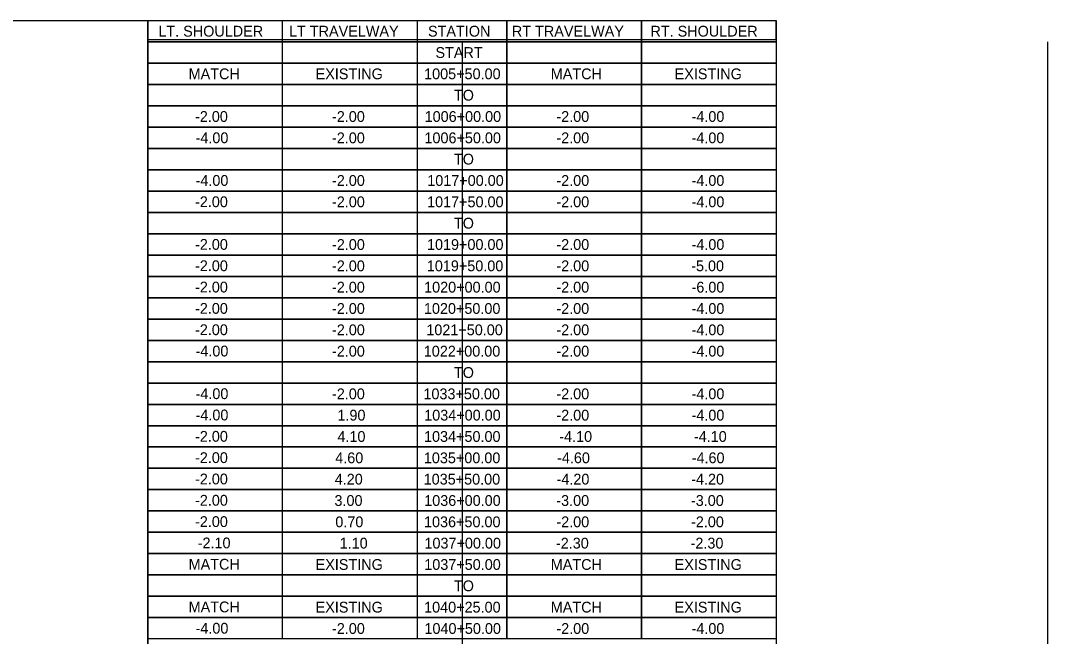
# Model space of a CAD drawing. Extents: x 1026502 to 1027102, y 781811 to 782040.
# Drawn here: x 1026944.94 to 1026990.71, y 781896.04 to 781923.49 of the extents above; entities that cross this region are included whole.
import ezdxf

# ---------------------------------------------------------------- set-up
doc = ezdxf.new("R2010")
doc.units = 0
for name, color, linetype in [('ANNOTATION', 7, 'Continuous'), ('BORDER', 7, 'Continuous'), ('DIMENSIONS', 7, 'Continuous')]:
    doc.layers.add(name, color=color, linetype=linetype)

msp = doc.modelspace()

# ---------------------------------------------------------------- linework, layer by layer
at = {"layer": 'ANNOTATION'}
for points in [[(1026917.619, 781923.493), (1026950.619, 781923.493), (1026950.619, 781846.737), (1026917.619, 781846.737)], [(1026950.619, 781923.493), (1026978.619, 781923.493), (1026978.619, 781869.32), (1026950.619, 781869.32)]]:
    msp.add_lwpolyline(points, close=True, dxfattribs=at)
at = {"layer": 'BORDER'}
for p, q in [((1026950.619, 781923.493), (1026950.619, 781922.648)), ((1026953.619, 781922.543), (1026950.619, 781922.543)), ((1026964.619, 781922.543), (1026964.619, 781816.098)), ((1026990.71, 781922.543), (1026990.71, 781816.098)), ((1026953.619, 781921.592), (1026950.619, 781921.592)), ((1026953.619, 781921.592), (1026950.619, 781921.592)), ((1026953.619, 781920.642), (1026950.619, 781920.642)), ((1026953.619, 781920.642), (1026950.619, 781920.642)), ((1026953.619, 781920.642), (1026956.619, 781920.642)), ((1026953.619, 781919.691), (1026950.619, 781919.691)), ((1026953.619, 781919.691), (1026950.619, 781919.691)), ((1026953.619, 781919.691), (1026956.619, 781919.691)), ((1026953.619, 781918.741), (1026950.619, 781918.741)), ((1026953.619, 781918.741), (1026950.619, 781918.741)), ((1026953.619, 781918.741), (1026956.619, 781918.741)), ((1026953.619, 781917.791), (1026950.619, 781917.791)), ((1026953.619, 781917.791), (1026950.619, 781917.791)), ((1026953.619, 781917.791), (1026956.619, 781917.791)), ((1026953.619, 781916.84), (1026950.619, 781916.84)), ((1026953.619, 781916.84), (1026950.619, 781916.84)), ((1026953.619, 781916.84), (1026956.619, 781916.84)), ((1026953.619, 781915.89), (1026950.619, 781915.89)), ((1026953.619, 781915.89), (1026950.619, 781915.89)), ((1026953.619, 781915.89), (1026956.619, 781915.89)), ((1026953.619, 781914.939), (1026950.619, 781914.939)), ((1026953.619, 781914.939), (1026950.619, 781914.939)), ((1026953.619, 781914.939), (1026956.619, 781914.939)), ((1026953.619, 781913.989), (1026950.619, 781913.989)), ((1026953.619, 781913.989), (1026950.619, 781913.989)), ((1026953.619, 781913.989), (1026956.619, 781913.989)), ((1026953.619, 781913.039), (1026950.619, 781913.039)), ((1026953.619, 781913.039), (1026950.619, 781913.039)), ((1026953.619, 781913.039), (1026956.619, 781913.039)), ((1026953.619, 781912.088), (1026950.619, 781912.088)), ((1026953.619, 781912.088), (1026950.619, 781912.088)), ((1026953.619, 781912.088), (1026956.619, 781912.088)), ((1026953.619, 781911.138), (1026950.619, 781911.138)), ((1026953.619, 781911.138), (1026950.619, 781911.138)), ((1026953.619, 781911.138), (1026956.619, 781911.138)), ((1026953.619, 781910.187), (1026950.619, 781910.187)), ((1026953.619, 781910.187), (1026950.619, 781910.187)), ((1026953.619, 781910.187), (1026956.619, 781910.187)), ((1026953.619, 781909.237), (1026950.619, 781909.237)), ((1026953.619, 781909.237), (1026950.619, 781909.237)), ((1026953.619, 781909.237), (1026956.619, 781909.237)), ((1026953.619, 781908.287), (1026950.619, 781908.287)), ((1026953.619, 781908.287), (1026950.619, 781908.287)), ((1026953.619, 781908.287), (1026956.619, 781908.287)), ((1026953.619, 781907.336), (1026950.619, 781907.336)), ((1026953.619, 781907.336), (1026950.619, 781907.336)), ((1026953.619, 781907.336), (1026956.619, 781907.336)), ((1026953.619, 781906.386), (1026950.619, 781906.386)), ((1026953.619, 781906.386), (1026950.619, 781906.386)), ((1026953.619, 781906.386), (1026956.619, 781906.386)), ((1026953.619, 781905.435), (1026950.619, 781905.435)), ((1026953.619, 781905.435), (1026950.619, 781905.435)), ((1026953.619, 781905.435), (1026956.619, 781905.435)), ((1026953.619, 781904.485), (1026950.619, 781904.485)), ((1026953.619, 781904.485), (1026950.619, 781904.485)), ((1026953.619, 781904.485), (1026956.619, 781904.485)), ((1026953.619, 781903.535), (1026950.619, 781903.535)), ((1026953.619, 781903.535), (1026950.619, 781903.535)), ((1026953.619, 781903.535), (1026956.619, 781903.535)), ((1026953.619, 781902.584), (1026950.619, 781902.584)), ((1026953.619, 781902.584), (1026950.619, 781902.584)), ((1026953.619, 781902.584), (1026956.619, 781902.584)), ((1026953.619, 781901.634), (1026950.619, 781901.634)), ((1026953.619, 781901.634), (1026950.619, 781901.634)), ((1026953.619, 781901.634), (1026956.619, 781901.634)), ((1026953.619, 781900.683), (1026950.619, 781900.683)), ((1026953.619, 781900.683), (1026950.619, 781900.683)), ((1026953.619, 781900.683), (1026956.619, 781900.683)), ((1026953.619, 781899.733), (1026950.619, 781899.733)), ((1026953.619, 781899.733), (1026950.619, 781899.733)), ((1026953.619, 781899.733), (1026956.619, 781899.733)), ((1026953.619, 781898.783), (1026950.619, 781898.783)), ((1026953.619, 781898.783), (1026950.619, 781898.783)), ((1026953.619, 781898.783), (1026956.619, 781898.783)), ((1026953.619, 781897.832), (1026950.619, 781897.832)), ((1026953.619, 781897.832), (1026950.619, 781897.832)), ((1026953.619, 781897.832), (1026956.619, 781897.832)), ((1026953.619, 781896.882), (1026950.619, 781896.882)), ((1026953.619, 781896.882), (1026950.619, 781896.882)), ((1026953.619, 781896.882), (1026956.619, 781896.882))]:
    msp.add_line(p, q, dxfattribs=at)
for points in [[(1026950.619, 781923.493), (1026978.619, 781923.493), (1026978.619, 781922.543), (1026950.619, 781922.543)], [(1026950.619, 781922.543), (1026978.619, 781922.543), (1026978.619, 781921.592), (1026950.619, 781921.592)], [(1026950.619, 781921.592), (1026978.619, 781921.592), (1026978.619, 781920.642), (1026950.619, 781920.642)], [(1026950.619, 781920.642), (1026978.619, 781920.642), (1026978.619, 781919.691), (1026950.619, 781919.691)], [(1026950.619, 781919.691), (1026978.619, 781919.691), (1026978.619, 781918.741), (1026950.619, 781918.741)], [(1026950.619, 781918.741), (1026978.619, 781918.741), (1026978.619, 781917.791), (1026950.619, 781917.791)], [(1026950.619, 781917.791), (1026978.619, 781917.791), (1026978.619, 781916.84), (1026950.619, 781916.84)], [(1026950.619, 781916.84), (1026978.619, 781916.84), (1026978.619, 781915.89), (1026950.619, 781915.89)], [(1026950.619, 781915.89), (1026978.619, 781915.89), (1026978.619, 781914.939), (1026950.619, 781914.939)], [(1026950.619, 781914.939), (1026978.619, 781914.939), (1026978.619, 781913.989), (1026950.619, 781913.989)], [(1026950.619, 781913.989), (1026978.619, 781913.989), (1026978.619, 781913.039), (1026950.619, 781913.039)], [(1026950.619, 781913.039), (1026978.619, 781913.039), (1026978.619, 781912.088), (1026950.619, 781912.088)], [(1026950.619, 781912.088), (1026978.619, 781912.088), (1026978.619, 781911.138), (1026950.619, 781911.138)], [(1026950.619, 781911.138), (1026978.619, 781911.138), (1026978.619, 781910.187), (1026950.619, 781910.187)], [(1026950.619, 781910.187), (1026978.619, 781910.187), (1026978.619, 781909.237), (1026950.619, 781909.237)], [(1026950.619, 781909.237), (1026978.619, 781909.237), (1026978.619, 781908.287), (1026950.619, 781908.287)], [(1026950.619, 781908.287), (1026978.619, 781908.287), (1026978.619, 781907.336), (1026950.619, 781907.336)], [(1026950.619, 781907.336), (1026978.619, 781907.336), (1026978.619, 781906.386), (1026950.619, 781906.386)], [(1026950.619, 781906.386), (1026978.619, 781906.386), (1026978.619, 781905.435), (1026950.619, 781905.435)], [(1026950.619, 781905.435), (1026978.619, 781905.435), (1026978.619, 781904.485), (1026950.619, 781904.485)], [(1026950.619, 781904.485), (1026978.619, 781904.485), (1026978.619, 781903.535), (1026950.619, 781903.535)], [(1026950.619, 781903.535), (1026978.619, 781903.535), (1026978.619, 781902.584), (1026950.619, 781902.584)], [(1026950.619, 781902.584), (1026978.619, 781902.584), (1026978.619, 781901.634), (1026950.619, 781901.634)], [(1026950.619, 781901.634), (1026978.619, 781901.634), (1026978.619, 781900.683), (1026950.619, 781900.683)], [(1026950.619, 781900.683), (1026978.619, 781900.683), (1026978.619, 781899.733), (1026950.619, 781899.733)], [(1026950.619, 781899.733), (1026978.619, 781899.733), (1026978.619, 781898.783), (1026950.619, 781898.783)], [(1026950.619, 781898.783), (1026978.619, 781898.783), (1026978.619, 781897.832), (1026950.619, 781897.832)], [(1026950.619, 781897.832), (1026978.619, 781897.832), (1026978.619, 781896.882), (1026950.619, 781896.882)], [(1026950.619, 781896.882), (1026978.619, 781896.882), (1026978.619, 781895.931), (1026950.619, 781895.931)]]:
    msp.add_lwpolyline(points, close=True, dxfattribs=at)
for points in [[(1026950.619, 781922.648), (1026978.619, 781922.648), (1026978.619, 781923.493)], [(1026962.619, 781923.493), (1026962.619, 781922.543), (1026956.619, 781922.543), (1026956.619, 781923.493)], [(1026966.619, 781923.493), (1026966.619, 781922.543), (1026962.619, 781922.543)], [(1026972.619, 781923.493), (1026972.619, 781922.543), (1026966.619, 781922.543), (1026966.619, 781923.493)], [(1026978.619, 781923.493), (1026978.619, 781922.543), (1026972.619, 781922.543), (1026972.619, 781923.493)], [(1026962.619, 781922.543), (1026962.619, 781921.592), (1026956.619, 781921.592), (1026956.619, 781922.543)], [(1026966.619, 781922.543), (1026966.619, 781921.592), (1026962.619, 781921.592)], [(1026972.619, 781922.543), (1026972.619, 781921.592), (1026966.619, 781921.592), (1026966.619, 781922.543)], [(1026978.619, 781922.543), (1026978.619, 781921.592), (1026972.619, 781921.592), (1026972.619, 781922.543)], [(1026962.619, 781921.592), (1026962.619, 781920.642), (1026956.619, 781920.642), (1026956.619, 781921.592)], [(1026966.619, 781921.592), (1026966.619, 781920.642), (1026962.619, 781920.642)], [(1026972.619, 781921.592), (1026972.619, 781920.642), (1026966.619, 781920.642), (1026966.619, 781921.592)], [(1026978.619, 781921.592), (1026978.619, 781920.642), (1026972.619, 781920.642), (1026972.619, 781921.592)], [(1026962.619, 781920.642), (1026962.619, 781919.691), (1026956.619, 781919.691), (1026956.619, 781920.642)], [(1026966.619, 781920.642), (1026966.619, 781919.691), (1026962.619, 781919.691)], [(1026972.619, 781920.642), (1026972.619, 781919.691), (1026966.619, 781919.691), (1026966.619, 781920.642)], [(1026978.619, 781920.642), (1026978.619, 781919.691), (1026972.619, 781919.691), (1026972.619, 781920.642)], [(1026962.619, 781919.691), (1026962.619, 781918.741), (1026956.619, 781918.741), (1026956.619, 781919.691)], [(1026966.619, 781919.691), (1026966.619, 781918.741), (1026962.619, 781918.741)], [(1026972.619, 781919.691), (1026972.619, 781918.741), (1026966.619, 781918.741), (1026966.619, 781919.691)], [(1026978.619, 781919.691), (1026978.619, 781918.741), (1026972.619, 781918.741), (1026972.619, 781919.691)], [(1026962.619, 781918.741), (1026962.619, 781917.791), (1026956.619, 781917.791), (1026956.619, 781918.741)], [(1026966.619, 781918.741), (1026966.619, 781917.791), (1026962.619, 781917.791)], [(1026972.619, 781918.741), (1026972.619, 781917.791), (1026966.619, 781917.791), (1026966.619, 781918.741)], [(1026978.619, 781918.741), (1026978.619, 781917.791), (1026972.619, 781917.791), (1026972.619, 781918.741)], [(1026962.619, 781917.791), (1026962.619, 781916.84), (1026956.619, 781916.84), (1026956.619, 781917.791)], [(1026966.619, 781917.791), (1026966.619, 781916.84), (1026962.619, 781916.84)], [(1026972.619, 781917.791), (1026972.619, 781916.84), (1026966.619, 781916.84), (1026966.619, 781917.791)], [(1026978.619, 781917.791), (1026978.619, 781916.84), (1026972.619, 781916.84), (1026972.619, 781917.791)], [(1026962.619, 781916.84), (1026962.619, 781915.89), (1026956.619, 781915.89), (1026956.619, 781916.84)], [(1026966.619, 781916.84), (1026966.619, 781915.89), (1026962.619, 781915.89)], [(1026972.619, 781916.84), (1026972.619, 781915.89), (1026966.619, 781915.89), (1026966.619, 781916.84)], [(1026978.619, 781916.84), (1026978.619, 781915.89), (1026972.619, 781915.89), (1026972.619, 781916.84)], [(1026962.619, 781915.89), (1026962.619, 781914.939), (1026956.619, 781914.939), (1026956.619, 781915.89)], [(1026966.619, 781915.89), (1026966.619, 781914.939), (1026962.619, 781914.939)], [(1026972.619, 781915.89), (1026972.619, 781914.939), (1026966.619, 781914.939), (1026966.619, 781915.89)], [(1026978.619, 781915.89), (1026978.619, 781914.939), (1026972.619, 781914.939), (1026972.619, 781915.89)], [(1026962.619, 781914.939), (1026962.619, 781913.989), (1026956.619, 781913.989), (1026956.619, 781914.939)], [(1026966.619, 781914.939), (1026966.619, 781913.989), (1026962.619, 781913.989)], [(1026972.619, 781914.939), (1026972.619, 781913.989), (1026966.619, 781913.989), (1026966.619, 781914.939)], [(1026978.619, 781914.939), (1026978.619, 781913.989), (1026972.619, 781913.989), (1026972.619, 781914.939)], [(1026962.619, 781913.989), (1026962.619, 781913.039), (1026956.619, 781913.039), (1026956.619, 781913.989)], [(1026966.619, 781913.989), (1026966.619, 781913.039), (1026962.619, 781913.039)], [(1026972.619, 781913.989), (1026972.619, 781913.039), (1026966.619, 781913.039), (1026966.619, 781913.989)], [(1026978.619, 781913.989), (1026978.619, 781913.039), (1026972.619, 781913.039), (1026972.619, 781913.989)], [(1026962.619, 781913.039), (1026962.619, 781912.088), (1026956.619, 781912.088), (1026956.619, 781913.039)], [(1026966.619, 781913.039), (1026966.619, 781912.088), (1026962.619, 781912.088)], [(1026972.619, 781913.039), (1026972.619, 781912.088), (1026966.619, 781912.088), (1026966.619, 781913.039)], [(1026978.619, 781913.039), (1026978.619, 781912.088), (1026972.619, 781912.088), (1026972.619, 781913.039)], [(1026962.619, 781912.088), (1026962.619, 781911.138), (1026956.619, 781911.138), (1026956.619, 781912.088)], [(1026966.619, 781912.088), (1026966.619, 781911.138), (1026962.619, 781911.138)], [(1026972.619, 781912.088), (1026972.619, 781911.138), (1026966.619, 781911.138), (1026966.619, 781912.088)], [(1026978.619, 781912.088), (1026978.619, 781911.138), (1026972.619, 781911.138), (1026972.619, 781912.088)], [(1026962.619, 781911.138), (1026962.619, 781910.187), (1026956.619, 781910.187), (1026956.619, 781911.138)], [(1026966.619, 781911.138), (1026966.619, 781910.187), (1026962.619, 781910.187)], [(1026972.619, 781911.138), (1026972.619, 781910.187), (1026966.619, 781910.187), (1026966.619, 781911.138)], [(1026978.619, 781911.138), (1026978.619, 781910.187), (1026972.619, 781910.187), (1026972.619, 781911.138)], [(1026962.619, 781910.187), (1026962.619, 781909.237), (1026956.619, 781909.237), (1026956.619, 781910.187)], [(1026966.619, 781910.187), (1026966.619, 781909.237), (1026962.619, 781909.237)], [(1026972.619, 781910.187), (1026972.619, 781909.237), (1026966.619, 781909.237), (1026966.619, 781910.187)], [(1026978.619, 781910.187), (1026978.619, 781909.237), (1026972.619, 781909.237), (1026972.619, 781910.187)], [(1026962.619, 781909.237), (1026962.619, 781908.287), (1026956.619, 781908.287), (1026956.619, 781909.237)], [(1026966.619, 781909.237), (1026966.619, 781908.287), (1026962.619, 781908.287)], [(1026972.619, 781909.237), (1026972.619, 781908.287), (1026966.619, 781908.287), (1026966.619, 781909.237)], [(1026978.619, 781909.237), (1026978.619, 781908.287), (1026972.619, 781908.287), (1026972.619, 781909.237)], [(1026962.619, 781908.287), (1026962.619, 781907.336), (1026956.619, 781907.336), (1026956.619, 781908.287)], [(1026966.619, 781908.287), (1026966.619, 781907.336), (1026962.619, 781907.336)], [(1026972.619, 781908.287), (1026972.619, 781907.336), (1026966.619, 781907.336), (1026966.619, 781908.287)], [(1026978.619, 781908.287), (1026978.619, 781907.336), (1026972.619, 781907.336), (1026972.619, 781908.287)], [(1026962.619, 781907.336), (1026962.619, 781906.386), (1026956.619, 781906.386), (1026956.619, 781907.336)], [(1026966.619, 781907.336), (1026966.619, 781906.386), (1026962.619, 781906.386)], [(1026972.619, 781907.336), (1026972.619, 781906.386), (1026966.619, 781906.386), (1026966.619, 781907.336)], [(1026978.619, 781907.336), (1026978.619, 781906.386), (1026972.619, 781906.386), (1026972.619, 781907.336)], [(1026962.619, 781906.386), (1026962.619, 781905.435), (1026956.619, 781905.435), (1026956.619, 781906.386)], [(1026966.619, 781906.386), (1026966.619, 781905.435), (1026962.619, 781905.435)], [(1026972.619, 781906.386), (1026972.619, 781905.435), (1026966.619, 781905.435), (1026966.619, 781906.386)], [(1026978.619, 781906.386), (1026978.619, 781905.435), (1026972.619, 781905.435), (1026972.619, 781906.386)], [(1026962.619, 781905.435), (1026962.619, 781904.485), (1026956.619, 781904.485), (1026956.619, 781905.435)], [(1026966.619, 781905.435), (1026966.619, 781904.485), (1026962.619, 781904.485)], [(1026972.619, 781905.435), (1026972.619, 781904.485), (1026966.619, 781904.485), (1026966.619, 781905.435)], [(1026978.619, 781905.435), (1026978.619, 781904.485), (1026972.619, 781904.485), (1026972.619, 781905.435)], [(1026962.619, 781904.485), (1026962.619, 781903.535), (1026956.619, 781903.535), (1026956.619, 781904.485)], [(1026966.619, 781904.485), (1026966.619, 781903.535), (1026962.619, 781903.535)], [(1026972.619, 781904.485), (1026972.619, 781903.535), (1026966.619, 781903.535), (1026966.619, 781904.485)], [(1026978.619, 781904.485), (1026978.619, 781903.535), (1026972.619, 781903.535), (1026972.619, 781904.485)], [(1026962.619, 781903.535), (1026962.619, 781902.584), (1026956.619, 781902.584), (1026956.619, 781903.535)], [(1026966.619, 781903.535), (1026966.619, 781902.584), (1026962.619, 781902.584)], [(1026972.619, 781903.535), (1026972.619, 781902.584), (1026966.619, 781902.584), (1026966.619, 781903.535)], [(1026978.619, 781903.535), (1026978.619, 781902.584), (1026972.619, 781902.584), (1026972.619, 781903.535)], [(1026962.619, 781902.584), (1026962.619, 781901.634), (1026956.619, 781901.634), (1026956.619, 781902.584)], [(1026966.619, 781902.584), (1026966.619, 781901.634), (1026962.619, 781901.634)], [(1026972.619, 781902.584), (1026972.619, 781901.634), (1026966.619, 781901.634), (1026966.619, 781902.584)], [(1026978.619, 781902.584), (1026978.619, 781901.634), (1026972.619, 781901.634), (1026972.619, 781902.584)], [(1026962.619, 781901.634), (1026962.619, 781900.683), (1026956.619, 781900.683), (1026956.619, 781901.634)], [(1026966.619, 781901.634), (1026966.619, 781900.683), (1026962.619, 781900.683)], [(1026972.619, 781901.634), (1026972.619, 781900.683), (1026966.619, 781900.683), (1026966.619, 781901.634)], [(1026978.619, 781901.634), (1026978.619, 781900.683), (1026972.619, 781900.683), (1026972.619, 781901.634)], [(1026962.619, 781900.683), (1026962.619, 781899.733), (1026956.619, 781899.733), (1026956.619, 781900.683)], [(1026966.619, 781900.683), (1026966.619, 781899.733), (1026962.619, 781899.733)], [(1026972.619, 781900.683), (1026972.619, 781899.733), (1026966.619, 781899.733), (1026966.619, 781900.683)], [(1026978.619, 781900.683), (1026978.619, 781899.733), (1026972.619, 781899.733), (1026972.619, 781900.683)], [(1026962.619, 781899.733), (1026962.619, 781898.783), (1026956.619, 781898.783), (1026956.619, 781899.733)], [(1026966.619, 781899.733), (1026966.619, 781898.783), (1026962.619, 781898.783)], [(1026972.619, 781899.733), (1026972.619, 781898.783), (1026966.619, 781898.783), (1026966.619, 781899.733)], [(1026978.619, 781899.733), (1026978.619, 781898.783), (1026972.619, 781898.783), (1026972.619, 781899.733)], [(1026962.619, 781898.783), (1026962.619, 781897.832), (1026956.619, 781897.832), (1026956.619, 781898.783)], [(1026966.619, 781898.783), (1026966.619, 781897.832), (1026962.619, 781897.832)], [(1026972.619, 781898.783), (1026972.619, 781897.832), (1026966.619, 781897.832), (1026966.619, 781898.783)], [(1026978.619, 781898.783), (1026978.619, 781897.832), (1026972.619, 781897.832), (1026972.619, 781898.783)], [(1026962.619, 781897.832), (1026962.619, 781896.882), (1026956.619, 781896.882), (1026956.619, 781897.832)], [(1026966.619, 781897.832), (1026966.619, 781896.882), (1026962.619, 781896.882)], [(1026972.619, 781897.832), (1026972.619, 781896.882), (1026966.619, 781896.882), (1026966.619, 781897.832)], [(1026978.619, 781897.832), (1026978.619, 781896.882), (1026972.619, 781896.882), (1026972.619, 781897.832)], [(1026962.619, 781896.882), (1026962.619, 781895.931), (1026956.619, 781895.931), (1026956.619, 781896.882)], [(1026966.619, 781896.882), (1026966.619, 781895.931), (1026962.619, 781895.931)], [(1026972.619, 781896.882), (1026972.619, 781895.931), (1026966.619, 781895.931), (1026966.619, 781896.882)], [(1026978.619, 781896.882), (1026978.619, 781895.931), (1026972.619, 781895.931), (1026972.619, 781896.882)]]:
    msp.add_lwpolyline(points, dxfattribs=at)

# ---------------------------------------------------------------- texts
at = {"layer": 'DIMENSIONS'}
for s, p in [('LT. SHOULDER', (1026951.086, 781922.778)), ('LT TRAVELWAY', (1026956.909, 781922.778)), ('STATION', (1026963.103, 781922.778)), ('RT TRAVELWAY', (1026966.841, 781922.778)), ('RT. SHOULDER', (1026973.017, 781922.778)), ('START', (1026963.435, 781921.827)), ('MATCH', (1026952.436, 781920.877)), ('EXISTING', (1026958.095, 781920.877)), ('1005+50.00', (1026962.93, 781920.877)), ('MATCH', (1026968.575, 781920.877)), ('EXISTING', (1026974.095, 781920.877)), ('TO', (1026964.26, 781919.926)), ('-2.00', (1026952.72, 781918.976)), ('-2.00', (1026958.825, 781918.975)), ('1006+00.00', (1026962.953, 781918.975)), ('-2.00', (1026968.825, 781918.975)), ('-4.00', (1026974.848, 781918.975)), ('-4.00', (1026952.745, 781918.026)), ('-2.00', (1026958.825, 781918.024)), ('1006+50.00', (1026962.945, 781918.024)), ('-2.00', (1026968.825, 781918.024)), ('-4.00', (1026974.848, 781918.024)), ('TO', (1026964.26, 781917.074)), ('-4.00', (1026952.745, 781916.125)), ('-2.00', (1026958.825, 781916.123)), ('1017+00.00', (1026963.07, 781916.123)), ('-2.00', (1026968.825, 781916.123)), ('-4.00', (1026974.848, 781916.123)), ('-2.00', (1026952.72, 781915.175)), ('-2.00', (1026958.825, 781915.172)), ('1017+50.00', (1026963.062, 781915.172)), ('-2.00', (1026968.825, 781915.172)), ('-4.00', (1026974.848, 781915.172)), ('TO', (1026964.26, 781914.221)), ('-2.00', (1026952.72, 781913.274)), ('-2.00', (1026958.825, 781913.27)), ('1019+00.00', (1026963.059, 781913.27)), ('-2.00', (1026968.825, 781913.27)), ('-4.00', (1026974.848, 781913.27)), ('-2.00', (1026952.72, 781912.323)), ('-2.00', (1026958.825, 781912.319)), ('1019+50.00', (1026963.051, 781912.319)), ('-2.00', (1026968.825, 781912.319)), ('-5.00', (1026974.833, 781912.319)), ('-2.00', (1026952.72, 781911.373)), ('-2.00', (1026958.825, 781911.369)), ('1020+00.00', (1026962.93, 781911.369)), ('-2.00', (1026968.825, 781911.369)), ('-6.00', (1026974.848, 781911.369)), ('-2.00', (1026952.72, 781910.423)), ('-2.00', (1026958.825, 781910.418)), ('1020+50.00', (1026962.922, 781910.418)), ('-2.00', (1026968.825, 781910.418)), ('-4.00', (1026974.848, 781910.418)), ('-2.00', (1026952.72, 781909.472)), ('-2.00', (1026958.825, 781909.467)), ('1021+50.00', (1026963.028, 781909.467)), ('-2.00', (1026968.825, 781909.467)), ('-4.00', (1026974.848, 781909.467)), ('-4.00', (1026952.745, 781908.522)), ('-2.00', (1026958.825, 781908.516)), ('1022+00.00', (1026962.915, 781908.516)), ('-2.00', (1026968.825, 781908.516)), ('-4.00', (1026974.848, 781908.516)), ('TO', (1026964.26, 781907.565)), ('-4.00', (1026952.745, 781906.621)), ('-2.00', (1026958.825, 781906.614)), ('1033+50.00', (1026962.9, 781906.614)), ('-2.00', (1026968.825, 781906.614)), ('-4.00', (1026974.848, 781906.614)), ('-4.00', (1026952.745, 781905.671)), ('1.90', (1026959.067, 781905.664)), ('1034+00.00', (1026962.934, 781905.664)), ('-2.00', (1026968.825, 781905.664)), ('-4.00', (1026974.848, 781905.664)), ('-2.00', (1026952.72, 781904.72)), ('4.10', (1026959.067, 781904.713)), ('1034+50.00', (1026962.926, 781904.713)), ('-4.10', (1026968.954, 781904.713)), ('-4.10', (1026974.954, 781904.713)), ('-2.00', (1026952.72, 781903.77)), ('4.60', (1026958.969, 781903.762)), ('1035+00.00', (1026962.919, 781903.762)), ('-4.60', (1026968.856, 781903.762)), ('-4.60', (1026974.856, 781903.762)), ('-2.00', (1026952.72, 781902.819)), ('4.20', (1026958.946, 781902.811)), ('1035+50.00', (1026962.911, 781902.811)), ('-4.20', (1026968.833, 781902.811)), ('-4.20', (1026974.833, 781902.811)), ('-2.00', (1026952.72, 781901.869)), ('3.00', (1026958.935, 781901.86)), ('1036+00.00', (1026962.934, 781901.86)), ('-3.00', (1026968.822, 781901.86)), ('-3.00', (1026974.822, 781901.86)), ('-2.00', (1026952.72, 781900.919)), ('0.70', (1026958.973, 781900.909)), ('1036+50.00', (1026962.926, 781900.909)), ('-2.00', (1026968.825, 781900.909)), ('-2.00', (1026974.825, 781900.909)), ('-2.10', (1026952.84, 781899.968)), ('1.10', (1026959.165, 781899.959)), ('1037+00.00', (1026962.945, 781899.959)), ('-2.30', (1026968.806, 781899.959)), ('-2.30', (1026974.806, 781899.959)), ('MATCH', (1026952.436, 781899.018)), ('EXISTING', (1026958.095, 781899.008)), ('1037+50.00', (1026962.937, 781899.008)), ('MATCH', (1026968.575, 781899.008)), ('EXISTING', (1026974.095, 781899.008)), ('TO', (1026964.26, 781898.057)), ('MATCH', (1026952.436, 781897.117)), ('EXISTING', (1026958.095, 781897.106)), ('1040+25.00', (1026962.93, 781897.106)), ('MATCH', (1026968.575, 781897.106)), ('EXISTING', (1026974.095, 781897.106)), ('-4.00', (1026952.745, 781896.167)), ('-2.00', (1026958.825, 781896.155)), ('1040+50.00', (1026962.945, 781896.155)), ('-2.00', (1026968.825, 781896.155)), ('-4.00', (1026974.848, 781896.155))]:
    msp.add_text(s, height=0.48, dxfattribs=at).set_placement(p)

doc.saveas('drawing.dxf')
